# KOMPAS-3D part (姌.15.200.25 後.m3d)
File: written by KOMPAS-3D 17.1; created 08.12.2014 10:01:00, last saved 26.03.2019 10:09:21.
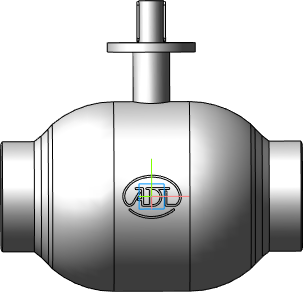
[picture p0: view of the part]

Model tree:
1. Операция без истории:4  (labels: Сталь 20  ГОСТ 1050-88)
